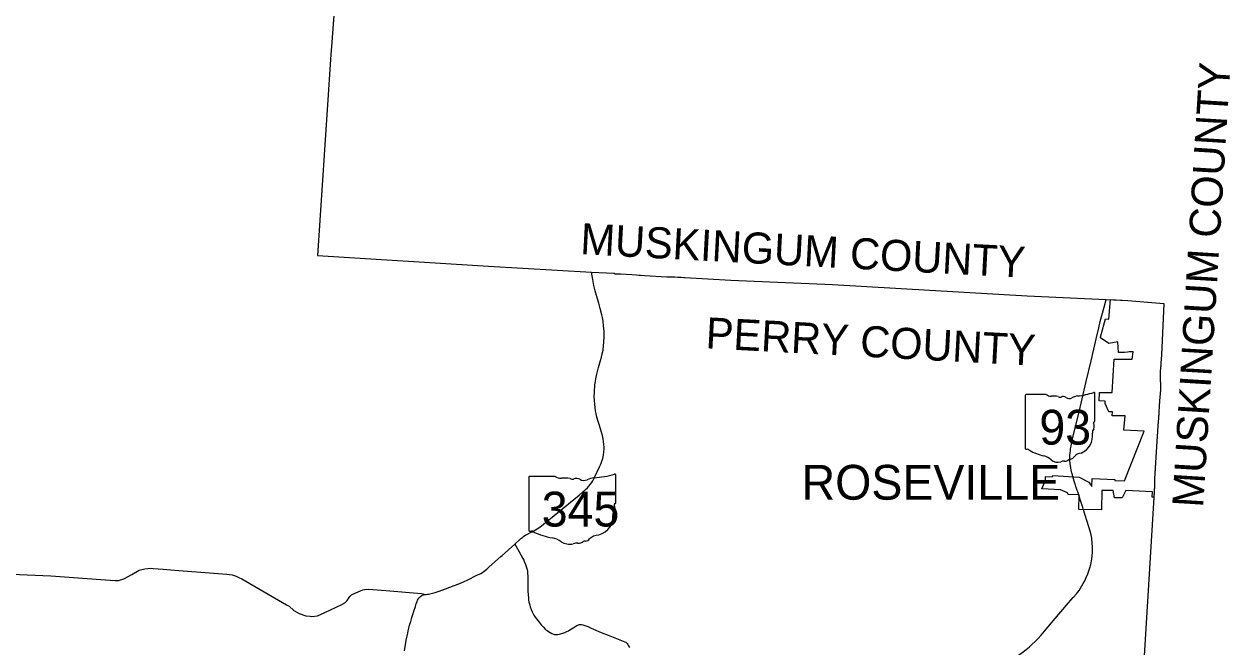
# Model space of a CAD drawing. Extents: x 1912787 to 2184787, y 543251 to 719251.
# Drawn here: x 2051715 to 2090543, y 650725 to 670769 of the extents above; entities that cross this region are included whole.
import ezdxf

# ---------------------------------------------------------------- set-up
doc = ezdxf.new("R2010")
doc.units = 0
for name, color, linetype in [('GM_X_Corporation', 7, 'Continuous'), ('GM_X_Corporation_Text', 7, 'Continuous'), ('GM_X_County', 7, 'Continuous'), ('GM_X_County_Text', 7, 'Continuous'), ('GM_X_State_Location', 7, 'Continuous'), ('GM_X_State_Route', 7, 'Continuous'), ('GM_X_State_Shield', 7, 'Continuous')]:
    doc.layers.add(name, color=color, linetype=linetype)

msp = doc.modelspace()

# ---------------------------------------------------------------- linework, layer by layer
at = {"layer": 'GM_X_Corporation'}
for p, q in [((2086650, 661270), (2086695, 661907)), ((2086695, 661907), (2087253, 661877)), ((2087253, 661877), (2088416, 661775)), ((2086379, 660697), (2086535, 661282)), ((2086535, 661282), (2086650, 661270)), ((2086378, 660668), (2086379, 660697)), ((2086645, 660486), (2086378, 660668)), ((2086932, 660541), (2086645, 660486)), ((2086954, 660200), (2086932, 660541)), ((2087031, 660197), (2086954, 660200)), ((2087153, 660202), (2087031, 660197)), ((2087251, 660211), (2087153, 660202)), ((2087303, 660221), (2087251, 660211)), ((2087425, 660220), (2087303, 660221)), ((2087392, 659982), (2087425, 660220)), ((2086751, 658910), (2086818, 659989)), ((2086818, 659989), (2087392, 659982)), ((2086338, 658646), (2086341, 658917)), ((2086341, 658917), (2086751, 658910)), ((2086526, 658634), (2086338, 658646)), ((2086525, 658560), (2086526, 658634)), ((2086647, 658287), (2086525, 658560)), ((2086760, 658285), (2086647, 658287)), ((2086757, 658159), (2086760, 658285)), ((2087169, 658165), (2086757, 658159)), ((2087133, 657705), (2087169, 658165)), ((2087783, 657664), (2087133, 657705)), ((2087152, 656073), (2087783, 657664)), ((2084602, 656092), (2084605, 656207)), ((2084605, 656207), (2084831, 656201)), ((2084831, 656201), (2084842, 656244)), ((2084842, 656244), (2085691, 656191)), ((2085691, 656191), (2085998, 656024)), ((2084491, 655807), (2084602, 656092)), ((2085086, 655778), (2084491, 655807)), ((2085998, 656024), (2086094, 655889)), ((2086094, 655889), (2086103, 656141)), ((2086103, 656141), (2086843, 656114)), ((2086843, 656114), (2086842, 656084)), ((2086842, 656084), (2087152, 656073)), ((2085312, 655681), (2085086, 655778)), ((2085338, 655626), (2085312, 655681)), ((2085688, 655620), (2085338, 655626)), ((2085680, 655150), (2085688, 655620)), ((2086418, 655763), (2086408, 655138)), ((2086788, 655757), (2086418, 655763)), ((2086829, 655525), (2086788, 655757)), ((2087078, 655521), (2086829, 655525)), ((2087187, 655757), (2087078, 655521)), ((2088053, 655715), (2087187, 655757)), ((2088042, 655543), (2088053, 655715)), ((2088089, 655540), (2088042, 655543)), ((2086408, 655138), (2085680, 655150))]:
    msp.add_line(p, q, dxfattribs=at)
msp.add_lwpolyline([(2088416, 661775), (2088336, 660120), (2088322, 659860), (2088319, 659812), (2088310, 659695), (2088303, 659612), (2088299, 659562), (2088298, 659506), (2088305, 659000), (2088281, 658645), (2088278, 658620), (2088268, 658504), (2088267, 658493), (2088261, 658411), (2088257, 658346), (2088251, 658265), (2088231, 657951), (2088227, 657874), (2088226, 657870), (2088214, 657653), (2088194, 657350), (2088116, 656131), (2088117, 655914), (2088089, 655540), (2088089, 655540)], dxfattribs=at)
at = {"layer": 'GM_X_County'}
msp.add_lwpolyline([(2061866, 673514), (2061628, 670188), (2061593, 669791), (2061163, 663317), (2066670, 662982), (2069990, 662786), (2070707, 662756), (2070717, 662749), (2070750, 662737), (2070775, 662733), (2070818, 662730), (2070916, 662727), (2071102, 662716), (2071283, 662709), (2071431, 662699), (2071508, 662693), (2071560, 662687), (2071695, 662683), (2072408, 662637), (2072452, 662639), (2072503, 662638), (2072516, 662638), (2072671, 662632), (2072768, 662625), (2072877, 662620), (2072959, 662618), (2072982, 662618), (2072987, 662619), (2074474, 662529), (2077743, 662384), (2084010, 662026), (2086561, 661911), (2087257, 661874), (2088416, 661775), (2088336, 660115), (2088322, 659856), (2088319, 659808), (2088310, 659690), (2088303, 659607), (2088299, 659558), (2088298, 659501), (2088305, 658995), (2088281, 658640), (2088277, 658616), (2088268, 658499), (2088267, 658488), (2088261, 658406), (2088257, 658341), (2088250, 658260), (2088231, 657946), (2088226, 657869), (2088226, 657865), (2088214, 657648), (2088194, 657345), (2088116, 656126), (2088117, 655909), (2088089, 655535), (2087468, 645340)], dxfattribs=at)
at = {"layer": 'GM_X_State_Route'}
for p, q in [((2067067, 653636), (2067106, 653670)), ((2055871, 653252), (2056188, 653226))]:
    msp.add_line(p, q, dxfattribs=at)
for points in [[(2068066, 654428), (2068070, 654430), (2068133, 654461), (2068231, 654519), (2068325, 654583), (2068440, 654673), (2069593, 655613), (2069798, 655791), (2069852, 655842), (2069890, 655885), (2069953, 655964), (2069986, 656010), (2070025, 656071), (2070084, 656176), (2070248, 656519), (2070277, 656583), (2070300, 656637), (2070322, 656702), (2070349, 656786), (2070372, 656890), (2070388, 656998), (2070391, 657085), (2070391, 657152), (2070386, 657240), (2070375, 657340), (2070363, 657425), (2070335, 657533), (2070306, 657634), (2070229, 657882), (2070192, 658006), (2070169, 658087), (2070151, 658163), (2070134, 658237), (2070119, 658325), (2070104, 658431), (2070092, 658527), (2070083, 658655), (2070076, 658792), (2070079, 658916), (2070083, 659007), (2070088, 659075), (2070098, 659160), (2070112, 659267), (2070127, 659349), (2070146, 659455), (2070166, 659547), (2070215, 659715), (2070280, 659946), (2070309, 660048), (2070332, 660153), (2070357, 660276), (2070377, 660438), (2070382, 660511), (2070393, 660738), (2070392, 660878), (2070376, 661061), (2070358, 661212), (2070340, 661323), (2070322, 661409), (2070268, 661618), (2070219, 661785), (2070146, 662034), (2070106, 662183), (2070063, 662361), (2070026, 662553), (2069991, 662783)], [(2085470, 656264), (2085452, 656330), (2085432, 656414), (2085417, 656498), (2085402, 656612), (2085393, 656734), (2085391, 656821), (2085394, 656887), (2085399, 656966), (2085406, 657040), (2085415, 657103), (2085429, 657183), (2085445, 657262), (2085462, 657343), (2085480, 657418), (2085685, 658293), (2085913, 659268), (2086071, 659929), (2086249, 660684), (2086321, 660994), (2086370, 661195), (2086492, 661662), (2086562, 661908)], [(2085628, 655762), (2085531, 656063), (2085483, 656213), (2085470, 656264)], [(2085805, 655213), (2085723, 655464), (2085643, 655717), (2085628, 655762)], [(2085491, 652313), (2085602, 652435), (2085685, 652544), (2085736, 652618), (2085823, 652764), (2085870, 652855), (2085920, 652958), (2085967, 653072), (2086005, 653177), (2086034, 653267), (2086062, 653380), (2086094, 653553), (2086106, 653664), (2086114, 653752), (2086117, 653856), (2086119, 653941), (2086111, 654068), (2086094, 654220), (2086073, 654328), (2086046, 654446), (2086005, 654590), (2085819, 655168), (2085805, 655213)], [(2067512, 654028), (2067675, 654176), (2067714, 654209), (2067763, 654250), (2067806, 654284), (2067857, 654318), (2067904, 654347), (2068066, 654428)], [(2067106, 653670), (2067308, 653851), (2067512, 654028)], [(2067512, 654028), (2067641, 653808), (2067774, 653574), (2067805, 653511), (2067832, 653456), (2067865, 653377), (2067887, 653314), (2067906, 653248), (2067920, 653176), (2067928, 653097), (2067934, 653004), (2067938, 652642), (2067938, 652517), (2067943, 652395), (2067953, 652302), (2067961, 652236), (2067973, 652159)], [(2066297, 653033), (2066377, 653068), (2066423, 653091), (2066475, 653123), (2066528, 653159), (2066612, 653227), (2066691, 653296), (2066875, 653465), (2067067, 653636)], [(2051310, 653069), (2052577, 653007), (2054191, 652896), (2054639, 652858), (2054751, 652864), (2054931, 652914), (2055186, 653058), (2055424, 653190), (2055598, 653238), (2055792, 653258), (2055871, 653252)], [(2056188, 653226), (2056559, 653190), (2057822, 653101), (2058247, 653065), (2058411, 653043), (2058549, 653003), (2058634, 652961), (2058725, 652917), (2060163, 652078), (2060248, 652032), (2060406, 651900), (2060572, 651799), (2060792, 651725), (2060926, 651709), (2060979, 651703), (2061161, 651729), (2061403, 651829), (2061945, 652085), (2062045, 652147), (2062121, 652217), (2062207, 652351), (2062253, 652399), (2062305, 652423), (2062471, 652497), (2062619, 652559), (2062673, 652571), (2062810, 652577), (2063362, 652543), (2064514, 652440), (2064560, 652429), (2064624, 652411)], [(2064624, 652411), (2064663, 652414), (2064701, 652419), (2064736, 652425), (2064781, 652435), (2064861, 652455), (2064947, 652480), (2065048, 652512), (2065199, 652563), (2065283, 652593), (2065559, 652698), (2065710, 652756), (2065859, 652818), (2066000, 652880), (2066297, 653033)], [(2064269, 651875), (2064314, 652020), (2064343, 652109), (2064369, 652180), (2064386, 652224), (2064404, 652259), (2064428, 652298), (2064458, 652329), (2064488, 652353), (2064520, 652374), (2064548, 652389), (2064578, 652399), (2064624, 652411)], [(2082595, 649704), (2082944, 649945), (2083140, 650069), (2083382, 650224), (2083617, 650375), (2083770, 650476), (2083885, 650562), (2083978, 650636), (2084076, 650716), (2084169, 650799), (2084274, 650899), (2084371, 650998), (2084467, 651105), (2084571, 651225), (2084856, 651562), (2085342, 652144), (2085491, 652313)], [(2067973, 652159), (2067986, 652106), (2068010, 652017), (2068043, 651929), (2068078, 651848), (2068130, 651746), (2068171, 651680), (2068210, 651626), (2068296, 651516), (2068363, 651434), (2068439, 651354), (2068494, 651299), (2068518, 651278), (2068555, 651248), (2068600, 651219), (2068656, 651187), (2068709, 651158), (2068762, 651136), (2068795, 651125), (2068835, 651119), (2068869, 651119), (2068902, 651124), (2068958, 651138), (2069127, 651192), (2069196, 651218), (2069249, 651243), (2069291, 651268), (2069344, 651304), (2069396, 651340), (2069450, 651375), (2069481, 651395), (2069513, 651413), (2069539, 651426), (2069567, 651436), (2069596, 651441), (2069618, 651444), (2069643, 651444), (2069667, 651441), (2069705, 651433), (2069768, 651414), (2069871, 651377), (2069932, 651353), (2069978, 651331), (2070293, 651190), (2070520, 651100), (2070796, 650993), (2071010, 650909), (2071061, 650887), (2071088, 650872), (2071115, 650852), (2071134, 650832), (2071158, 650804), (2071182, 650757), (2071209, 650704)], [(2063961, 650596), (2064004, 650864), (2064020, 650940), (2064067, 651167), (2064083, 651245), (2064105, 651329), (2064130, 651420), (2064163, 651538), (2064204, 651673), (2064236, 651770), (2064269, 651875)]]:
    msp.add_lwpolyline(points, dxfattribs=at)
at = {"layer": 'GM_X_State_Shield'}
for p, q in [((2083951, 658816), (2083951, 657115)), ((2084629, 658846), (2083973, 658846)), ((2086192, 657998), (2086192, 658888)), ((2086192, 657998), (2086192, 657998)), ((2067965, 656180), (2067965, 654479)), ((2068813, 656209), (2067993, 656209)), ((2070767, 655362), (2070767, 656251)), ((2070767, 655362), (2070767, 655362))]:
    msp.add_line(p, q, dxfattribs=at)
for centre, radius, start, end in [((2085394, 661165), 2377, 275.8445, 288.9065), ((2086168, 658892), 25, 351.8621, 97.738), ((2083977, 658820), 26, 98.1301, 188.1301), ((2084786, 659043), 252, 231.6195, 271.1119), ((2084869, 657891), 904, 80.4867, 94.9883), ((2085075, 658829), 72.7, 219.7921, 297.1024), ((2085181, 658632), 151, 54.4667, 119.1411), ((2085376, 658902), 182, 233.8562, 294.8282), ((2085697, 658326), 478, 97.3462, 120.7689), ((2086282, 657626), 169, 136.8065, 186.9296), ((2086187, 657933), 38.6, 107.944, 210.337), ((2085941, 657820), 232, 340.033, 23.6496), ((2086166, 657995), 26.7, 289.6038, 7.7341), ((2085527, 657512), 595, 292.3089, 8.9858), ((2083977, 657112), 26.2, 171.9584, 258.3066), ((2083981, 657286), 200, 267.339, 280.6039), ((2084022, 657017), 72.1, 29.7484, 93.2717), ((2084932, 658546), 1716, 240.4129, 257.1985), ((2085778, 656638), 326, 94.4031, 142.5768), ((2084420, 656351), 537, 47.1842, 75.836), ((2085001, 657009), 341, 230.7004, 286.2918), ((2085198, 656421), 280, 85.6951, 111.2099), ((2085223, 656881), 182, 268.777, 315.5493), ((2085387, 656717), 51.1, 65.7517, 132.6484), ((2085365, 656950), 192, 282.8732, 323.2771)]:
    msp.add_arc(centre, radius, start, end, dxfattribs=at)
for centre, major_axis, start_param, end_param in [((2067997, 656184), (32.5, 0), 1.712693, 3.28349), ((2069009, 656407), (315, 0), 4.042523, 4.731795), ((2069769, 658529), (2971, 0), 4.814394, 5.042369), ((2070736, 656255), (31.2, 0), 6.141152, 7.989035), ((2069113, 655254), (1130, 0), 1.404758, 1.657858), ((2069370, 656192), (90.8, 0), 3.836095, 5.185415), ((2069503, 655996), (189, 0), 0.950623, 2.079405), ((2069747, 656265), (227, 0), 4.081561, 5.145723), ((2070148, 655690), (598, 0), 1.699011, 2.107814), ((2070879, 654989), (211, 0), 2.387724, 3.262537), ((2070760, 655296), (48.3, 0), 1.883978, 3.671073), ((2070453, 655184), (290, 0), 5.934695, 6.695948), ((2070734, 655358), (33.4, 0), 5.05454, 6.418171), ((2069935, 654876), (743, 0), 5.101752, 6.440018), ((2067998, 654475), (32.7, 0), 3.00124, 4.508301), ((2068003, 654649), (250, 0), 4.665946, 4.897461), ((2068054, 654381), (90.1, 0), 0.519207, 1.627899), ((2069191, 655909), (2146, 0), 4.195997, 4.488961), ((2070249, 654001), (407, 0), 1.647645, 2.488434), ((2068552, 653715), (671, 0), 0.823519, 1.323587), ((2069278, 654372), (426, 0), 4.026481, 4.996735), ((2069524, 653784), (350, 0), 1.495662, 1.94098), ((2069555, 654245), (227, 0), 4.691044, 5.507374), ((2069760, 654080), (63.9, 0), 1.147584, 2.315152), ((2069733, 654314), (240, 0), 4.937069, 5.64225)]:
    msp.add_ellipse(centre, major_axis=major_axis, ratio=0.8, start_param=start_param, end_param=end_param, dxfattribs=at)

# ---------------------------------------------------------------- texts
at = {"layer": 'GM_X_Corporation_Text'}
msp.add_text('ROSEVILLE', height=1120, rotation=0, dxfattribs=at).set_placement((2076751, 655462))
at = {"layer": 'GM_X_County_Text'}
for s, rotation, p in [('MUSKINGUM COUNTY', 86.4606, (2089681, 655192)), ('MUSKINGUM COUNTY', 356.9521, (2069610, 663366)), ('PERRY COUNTY', 356.9521, (2073646, 660337))]:
    msp.add_text(s, height=1000, rotation=rotation, dxfattribs=at).set_placement(p)
at = {"layer": 'GM_X_State_Location'}
for s, p in [('s', (2085392, 657738)), ('r', (2085392, 657738)), ('s', (2068879, 654913)), ('r', (2068879, 654913))]:
    msp.add_text(s, height=1, dxfattribs=at).set_placement(p)
for s, p in [('93', (2085140, 657665)), ('345', (2068526, 654840))]:
    msp.add_text(s, height=1, rotation=0, dxfattribs=at).set_placement(p)
at = {"layer": 'GM_X_State_Shield'}
for s, p in [('93', (2084407, 657235)), ('345', (2068383, 654599))]:
    msp.add_text(s, height=1120.7, dxfattribs=at).set_placement(p)

doc.saveas('drawing.dxf')
